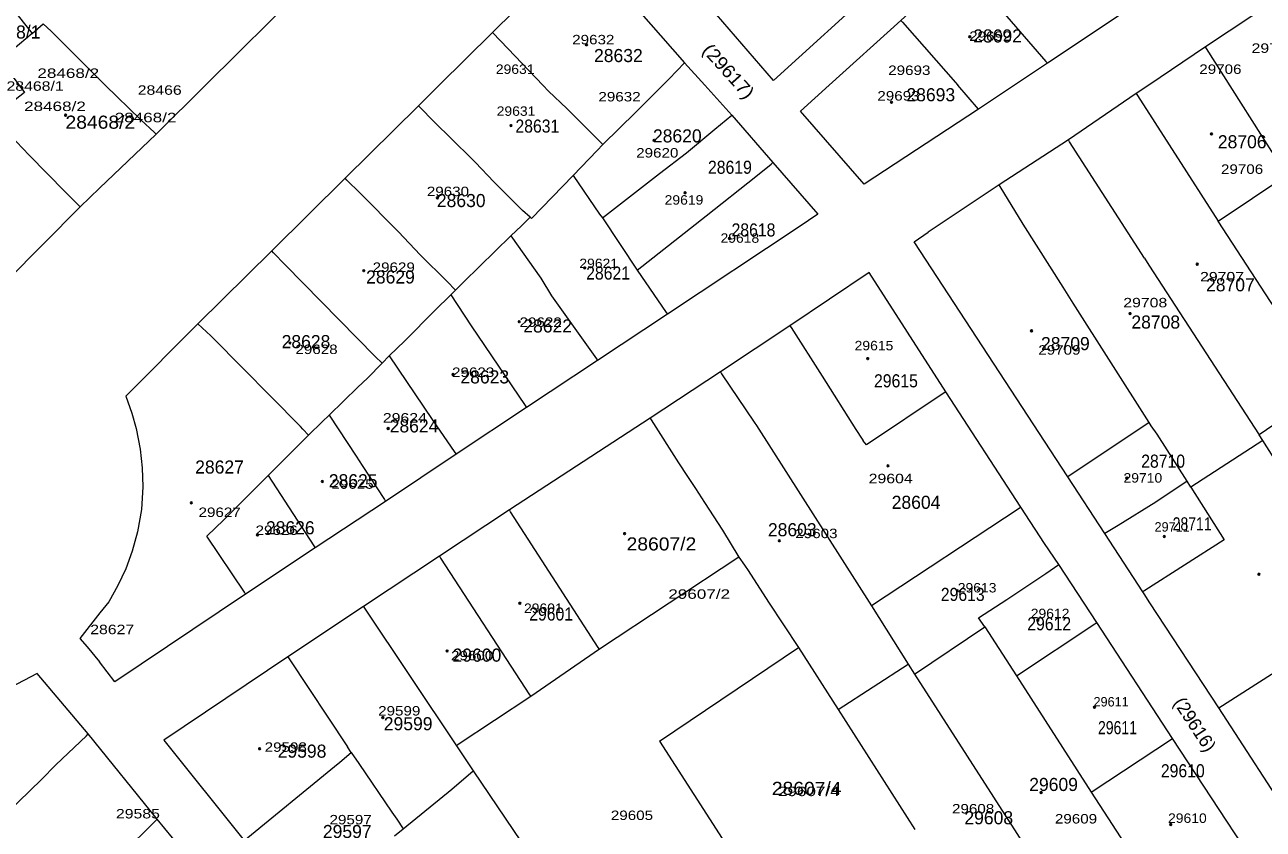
# Model space of a CAD drawing. Extents: x 650553 to 652508, y 239277 to 241647.
# Drawn here: x 651729.3 to 652069.7, y 240545.4 to 240766.6 of the extents above; entities that cross this region are included whole.
import ezdxf

# ---------------------------------------------------------------- set-up
doc = ezdxf.new("R2010")
doc.units = 0
doc.header["$PDMODE"] = 32
doc.header["$PDSIZE"] = 0.5
for name, color, linetype in [('19', 7, 'Continuous'), ('20', 7, 'Continuous'), ('6', 7, 'Continuous')]:
    doc.layers.add(name, color=color, linetype=linetype)
doc.layers.add('3', color=7, linetype='Continuous', lineweight=13)
doc.layers.add('5', color=7, linetype='Continuous', lineweight=13)

msp = doc.modelspace()

# ---------------------------------------------------------------- linework, layer by layer
at = {"layer": '3'}
for p, q in [((651744.578, 240716.581), (651749.871, 240721.656)), ((651746.467, 240595.607), (651749.932, 240591.408)), ((651754.072, 240585.965), (651749.932, 240591.408)), ((651767.56, 240569.86), (651789.69, 240542.31))]:
    msp.add_line(p, q, dxfattribs=at)
for points in [[(651950.46, 240750), (651970.1, 240767.82), (651986.91, 240783.26), (652001.01, 240795.81), (652014.98, 240808.48), (652029.04, 240821.24)], [(652130.48, 240811.26), (652125, 240807.76), (652110.91, 240798.75), (652092.01, 240785.99), (652073.09, 240773.31), (652053.84, 240760.57)], [(651857.87, 240764.46), (651882.29, 240788.58), (651910.691, 240756.161)], [(652058.39, 240788.05), (652042.27, 240777.48), (652026.22, 240766.64), (652010.4, 240756.05)], [(651963.94, 240777.64), (651935.1, 240751.32), (651917.67, 240771.45)], [(651805.82, 240776.71), (651779.01, 240750), (651765.5, 240736.54), (651749.871, 240721.656)], [(651857.87, 240764.46), (651843.25, 240750), (651837.57, 240744.38), (651817.39, 240724.43), (651797.25, 240704.42), (651776.92, 240684.41)], [(652053.84, 240760.57), (652038.24, 240750), (652034.83, 240747.69), (652016.18, 240734.96), (651997.1, 240722.64), (651977.65, 240709.59)], [(651910.691, 240756.161), (651916.23, 240750), (651923.66, 240741.74)], [(652010.4, 240756.05), (652001.33, 240750), (651991.49, 240743.44)], [(651991.49, 240743.44), (651960.07, 240722.77), (651942.55, 240742.83), (651950.46, 240750)], [(651923.66, 240741.74), (651934.97, 240728.71), (651947.34, 240714.57)], [(651666.816, 240692.253), (651670.475, 240694.498), (651675.984, 240697.224), (651681.411, 240699.022), (651686.904, 240700.185), (651694.099, 240701.383), (651699.482, 240701.668), (651705.326, 240701.397), (651710.373, 240700.626), (651715.395, 240699.613), (651720.434, 240697.99), (651724.445, 240696.209), (651744.578, 240716.581)], [(651947.34, 240714.57), (651942.18, 240711.07), (651905.96, 240687.02), (651886.79, 240674.3), (651867.2, 240661.39), (651847.91, 240648.53), (651828.5, 240635.58), (651809.15, 240622.82), (651790.027, 240610.062), (651754.072, 240585.965)], [(652016, 240642.3), (651973.78, 240706.91), (651977.65, 240709.59)], [(652013.5, 240618.17), (652009.59, 240623.96), (652003.11, 240633.96), (651982.48, 240665.71), (651961.39, 240698.5), (651939.62, 240683.88), (651920.51, 240671.17), (651901.2, 240658.49), (651862.54, 240633.2), (651843.29, 240620.48), (651822.42, 240606.7), (651801.69, 240592.79), (651767.56, 240569.86)], [(651776.92, 240684.41), (651757.09, 240664.52), (651758.77, 240659.87), (651759.98, 240655.65), (651761.09, 240649.96), (651761.61, 240644.75), (651761.79, 240639.59), (651761.41, 240633.29), (651760.36, 240627.15), (651758.86, 240621.88), (651757.16, 240616.98), (651754.97, 240612.43), (651752.42, 240607.99), (651750, 240604.91)], [(652057.49, 240578.77), (652038.51, 240607.71), (652036.94, 240610.19), (652036.66, 240610.72), (652026.17, 240626.69), (652016, 240642.3)], [(652044.73, 240570.4), (652023.96, 240602.27), (652013.5, 240618.17)], [(651750, 240604.91), (651744.473, 240597.87), (651746.467, 240595.607)], [(651732.727, 240588.221), (651729.118, 240586.307), (651725.471, 240584.379), (651722.848, 240583.22), (651719.197, 240581.891), (651716.775, 240581.139), (651714.429, 240580.567), (651712.373, 240580.275), (651712.25, 240579.538), (651708.175, 240579.209)], [(651780.52, 240530.19), (651765.75, 240548.18), (651746.79, 240571.618), (651732.727, 240588.221)], [(652100.82, 240560.71), (652078.69, 240546.12), (652057.49, 240578.77)], [(652043.65, 240523), (652066.18, 240537.76), (652044.73, 240570.4)]]:
    msp.add_lwpolyline(points, dxfattribs=at)
at = {"layer": '5'}
for p, q in [((651750, 240751.45), (651751.49, 240750)), ((651991.49, 240743.44), (651985.73, 240750)), ((651730.541, 240730.757), (651720.55, 240741.246)), ((651865.6, 240716.13), (651866.13, 240715.54)), ((651868.23, 240713.72), (651866.13, 240715.54)), ((651948.48, 240670.01), (651957.77, 240655.29)), ((652069.57, 240652.28), (652068.55, 240653.87)), ((651993.19, 240601.05), (652001.94, 240587.56)), ((651952.88, 240578.32), (651974, 240545.35)), ((651789.69, 240542.31), (651814.44, 240562.63)), ((652022.45, 240555.62), (652043.65, 240523))]:
    msp.add_line(p, q, dxfattribs=at)
for points in [[(651986.91, 240783.26), (651987.342, 240782.76), (652009.968, 240756.55), (652010.4, 240756.05)], [(651718.3, 240780.69), (651718.697, 240780.19), (651731.34, 240764.27), (651734.39, 240766.92), (651736.58, 240764.83), (651750, 240751.45)], [(651970.1, 240767.82), (651970.539, 240767.32), (651985.73, 240750)], [(651731.34, 240764.27), (651722.71, 240756.86), (651729.289, 240747.993), (651720.55, 240741.246)], [(651857.87, 240764.46), (651862.22, 240760.01), (651871.73, 240750)], [(652076.22, 240725.27), (652054.157, 240760.07), (652053.84, 240760.57)], [(651904.71, 240750), (651906.48, 240751.76), (651910.691, 240756.161)], [(651765.5, 240736.54), (651765, 240737.001), (651761.25, 240740.46), (651751.49, 240750)], [(651888.25, 240733.71), (651885.65, 240736.28), (651878.32, 240743.59), (651873.27, 240748.38), (651871.73, 240750)], [(651880.04, 240725.22), (651886.64, 240732.01), (651888.25, 240733.71), (651897.3, 240742.64), (651904.71, 240750)], [(652034.83, 240747.69), (652035.151, 240747.19), (652057.31, 240712.66)], [(651841.7, 240740.11), (651838.054, 240743.88), (651837.57, 240744.38)], [(651865.6, 240716.13), (651858.27, 240723.42), (651853.26, 240728.75), (651852.15, 240729.9), (651841.7, 240740.11)], [(651888.08, 240713.51), (651903.8, 240725.71), (651911.17, 240731.38), (651919.02, 240737.96), (651923.66, 240741.74)], [(652037.1, 240702.45), (652016.502, 240734.46), (652016.18, 240734.96)], [(651744.578, 240716.581), (651740.465, 240720.712), (651730.541, 240730.757)], [(651930.25, 240724.94), (651934.47, 240728.311), (651934.97, 240728.71)], [(651821.44, 240720.41), (651817.89, 240723.934), (651817.39, 240724.43)], [(651868.23, 240713.72), (651868.57, 240713.35), (651880.04, 240725.22)], [(651880.04, 240725.22), (651887.27, 240714.51), (651888.08, 240713.51), (651897.63, 240699.15)], [(651897.63, 240699.15), (651916.65, 240714.13), (651930.25, 240724.94)], [(652087.23, 240666.57), (652057.31, 240712.66), (652076.22, 240725.27)], [(651846.43, 240692.37), (651847.72, 240693.68), (651845.46, 240696.06), (651838.05, 240703.4), (651832.05, 240709.67), (651821.44, 240720.41)], [(652003.7, 240711.83), (651997.405, 240722.14), (651997.1, 240722.64)], [(651862.95, 240708.59), (651865.85, 240711.33), (651868.23, 240713.72)], [(652038.38, 240657.23), (652017.48, 240690.05), (652014.73, 240694.44), (652011.03, 240700.23), (652003.7, 240711.83)], [(651847.72, 240693.68), (651850.03, 240695.94), (651862.95, 240708.59), (651871.21, 240696.93), (651874.12, 240692.11)], [(651800.95, 240700.6), (651797.734, 240703.92), (651797.25, 240704.42)], [(651827.55, 240673.6), (651825.68, 240675.45), (651800.95, 240700.6)], [(651897.63, 240699.15), (651905.617, 240687.52), (651905.96, 240687.02)], [(652037.1, 240702.45), (652038.26, 240700.55), (652068.55, 240653.87)], [(651829.53, 240675.62), (651833.78, 240679.76), (651842.08, 240688.08), (651846.43, 240692.37), (651852.05, 240683.86)], [(651874.12, 240692.11), (651886.434, 240674.8), (651886.79, 240674.3)], [(651807.29, 240653.82), (651805.74, 240655.42), (651805.14, 240656.12), (651780.99, 240680.55), (651780.44, 240681.06), (651776.92, 240684.41)], [(651852.05, 240683.86), (651866.863, 240661.89), (651867.2, 240661.39)], [(651939.62, 240683.88), (651939.939, 240683.38), (651948.48, 240670.01)], [(651813.01, 240659.27), (651820.88, 240666.99), (651823.5, 240669.49), (651827.55, 240673.6), (651829.53, 240675.62), (651841.34, 240658.07)], [(651920.51, 240671.17), (651920.848, 240670.67), (651929.83, 240657.38)], [(651982.48, 240665.71), (651981.98, 240665.377), (651960.64, 240651.16), (651960.251, 240651.64), (651959.762, 240652.244)], [(652125, 240607.14), (652087.23, 240666.57), (652068.55, 240653.87)], [(651796.24, 240642.66), (651807.29, 240653.82), (651811.12, 240657.41), (651813.01, 240659.27), (651820.43, 240648.01), (651822.11, 240645.42)], [(651901.2, 240658.49), (651901.519, 240657.99), (651909.04, 240646.21)], [(651841.34, 240658.07), (651847.566, 240649.03), (651847.91, 240648.53)], [(651929.83, 240657.38), (651930.41, 240656.42), (651962.01, 240606.81)], [(651957.77, 240655.29), (651959.503, 240652.64), (651959.762, 240652.244)], [(652048.8, 240641.09), (652040.52, 240654.06), (652038.94, 240656.3), (652038.38, 240657.23), (652016, 240642.3)], [(652057.49, 240578.77), (652079.86, 240593.13), (652099.1, 240605.65), (652069.57, 240652.28), (652049.84, 240639.46)], [(651822.11, 240645.42), (651828.175, 240636.08), (651828.5, 240635.58)], [(651909.04, 240646.21), (651911.45, 240642.39), (651913.67, 240639.07), (651916.16, 240635.23), (651921.09, 240627.61), (651925.63, 240620.27), (651927.18, 240618.02), (651928.13, 240616.53), (651933.75, 240607.84), (651941.96, 240595.43)], [(651784.02, 240630.46), (651789.37, 240635.83), (651796.24, 240642.66)], [(651796.24, 240642.66), (651808.825, 240623.32), (651809.15, 240622.82)], [(652049.84, 240639.46), (652048.8, 240641.09), (652040.21, 240635.39), (652029.8, 240628.89)], [(652049.84, 240639.46), (652058.97, 240624.95), (652037.16, 240611.039), (652036.66, 240610.72)], [(651887.294, 240594.906), (651886.971, 240595.406), (651862.863, 240632.7), (651862.54, 240633.2)], [(652003.11, 240633.96), (652002.61, 240633.63), (651962.01, 240606.81)], [(651790.027, 240610.062), (651789.692, 240610.562), (651779.37, 240625.96), (651784.02, 240630.46)], [(652029.8, 240628.89), (652026.67, 240626.993), (652026.17, 240626.69)], [(651843.29, 240620.48), (651843.615, 240619.98), (651868.076, 240582.401), (651868.401, 240581.901)], [(651925.63, 240620.27), (651887.294, 240594.906), (651868.401, 240581.901)], [(651999.24, 240608.58), (652009.97, 240615.73), (652013.5, 240618.17)], [(651993.19, 240601.05), (651991.48, 240603.59), (651999.24, 240608.58)], [(651822.42, 240606.7), (651822.753, 240606.2), (651847.965, 240568.367), (651852.61, 240561.44)], [(651962.01, 240606.81), (651972.09, 240590.78), (651973.9, 240588.07), (651993.19, 240601.05)], [(652001.94, 240587.56), (652023.46, 240601.936), (652023.96, 240602.27)], [(651903.75, 240569.66), (651941.96, 240595.43), (651952.88, 240578.32), (651972.09, 240590.78)], [(651801.69, 240592.79), (651802.021, 240592.29), (651818.03, 240568.09)], [(651973.9, 240588.07), (652023.66, 240510.43), (652023.98, 240509.93)], [(652001.94, 240587.56), (652022.45, 240555.62), (652044.73, 240570.4)], [(651868.401, 240581.901), (651848.465, 240568.698), (651847.965, 240568.367)], [(651737.908, 240563.103), (651746.29, 240571.139), (651746.79, 240571.618)], [(651814.44, 240562.63), (651815.9, 240563.86), (651819.05, 240566.5), (651818.03, 240568.09)], [(651819.05, 240566.5), (651821.12, 240563.53), (651830.19, 240550.13), (651831.59, 240548.15), (651833.38, 240545.52)], [(651903.75, 240569.66), (651935.56, 240520.19), (651948.78, 240500)], [(651684.3, 240509.906), (651691.776, 240517.523), (651698.788, 240524.311), (651699.785, 240525.447), (651704.534, 240530.177), (651722.068, 240547.369), (651727.626, 240552.993), (651733.93, 240559.128), (651737.908, 240563.103)], [(651831, 240543.63), (651833.38, 240545.52), (651846.72, 240556.46), (651852.61, 240561.44), (651865.79, 240541.92), (651862.49, 240539.35), (651861.77, 240538.68)], [(651765.75, 240548.18), (651765.25, 240547.685), (651756.07, 240538.6), (651749.902, 240532.663)]]:
    msp.add_lwpolyline(points, dxfattribs=at)
at = {"layer": '6'}
for p in [(651883.718, 240761.145), (651989.059, 240763.35), (651967.565, 240745.295), (651740.567, 240741.75), (651862.976, 240738.905), (652055.482, 240736.615), (651902.341, 240734.835), (651910.805, 240720.445), (651842.744, 240719.03), (651923.024, 240707.865), (651822.493, 240699.015), (651883.215, 240699.76), (652051.571, 240700.78), (652033.102, 240687.21), (651865.244, 240684.99), (652006.029, 240682.47), (651802.237, 240679.12), (651961.008, 240674.83), (651847.05, 240670.45), (651829.235, 240655.6), (651966.588, 240645.345), (651811.121, 240641.045), (652032.233, 240641.96), (651775.127, 240635.187), (651793.315, 240626.361), (651894.198, 240626.698), (651936.724, 240624.745), (652042.527, 240625.905), (652068.52, 240615.525), (651985.635, 240611.015), (651865.413, 240607.55), (652007.768, 240602.865), (651845.426, 240594.423), (652023.317, 240578.945), (651827.765, 240576.11), (651793.896, 240567.55), (652008.658, 240555.49), (652044.276, 240546.7)]:
    msp.add_point(p, dxfattribs=at)

# ---------------------------------------------------------------- texts
at = {"layer": '19'}
for s, p in [('28468/1', (651716.245, 240762.834)), ('28692', (651990.006, 240761.756)), ('28632', (651885.794, 240756.368)), ('28693', (651971.647, 240745.591)), ('28620', (651901.992, 240734.275)), ('28706', (652057.232, 240732.659)), ('28630', (651842.596, 240716.495)), ('28629', (651823.158, 240695.481)), ('28707', (652053.993, 240693.325)), ('28622', (651866.355, 240682.009)), ('28708', (652033.473, 240683.087)), ('28628', (651799.939, 240677.699)), ('28709', (652008.636, 240677.16)), ('28623', (651849.076, 240668)), ('28624', (651829.636, 240654.529)), ('28627', (651776.181, 240643.215)), ('28625', (651812.899, 240639.442)), ('28604', (651967.596, 240633.516)), ('28626', (651795.62, 240626.51)), ('28603', (651933.579, 240625.972)), ('29600', (651846.916, 240591.487)), ('29599', (651828.017, 240572.628)), ('29598', (651798.859, 240565.084)), ('29609', (652005.396, 240555.925)), ('29608', (651987.577, 240546.765)), ('29597', (651811.279, 240542.993))]:
    msp.add_text(s, height=3.6, dxfattribs=at).set_placement(p)
at = {"layer": '19', "width": 1.1}
msp.add_text('(29617)', height=3.6, rotation=311.972, dxfattribs=at).set_placement((651915.315, 240759.445))
at = {"layer": '19'}
for s, width, p in [('28468/2', 1.1, (651740.542, 240738.048)), ('28631', 0.9, (651864.196, 240736.97)), ('28619', 0.9, (651917.111, 240725.654)), ('28618', 0.9, (651923.59, 240708.412)), ('28621', 0.9, (651883.634, 240696.558)), ('29615', 0.9, (651962.739, 240666.923)), ('28710', 0.9, (652036.173, 240644.831)), ('28711', 0.8, (652044.813, 240627.588)), ('28607/2', 1.1, (651894.745, 240622.066)), ('29613', 0.9, (651981.097, 240608.191)), ('29601', 0.9, (651867.976, 240602.802)), ('29612', 0.9, (652004.856, 240600.109)), ('29611', 0.8, (652024.295, 240571.551)), ('29610', 0.9, (652041.573, 240559.697)), ('28607/4', 1.1, (651934.658, 240554.847))]:
    msp.add_text(s, height=3.6, dxfattribs=dict(at, width=width)).set_placement(p)
msp.add_text('(29616)', height=3.6, rotation=303.093, dxfattribs=at).set_placement((652044.894, 240580.221))
at = {"layer": '20'}
for s, width, p in [('29632', 1.2, (651879.791, 240761.248)), ('29692', 1.2, (651988.89, 240762.205)), ('29705', 1.25, (652066.496, 240758.902)), ('28468/2', 1.35, (651732.817, 240752.015)), ('29631', 1.1, (651858.803, 240753.111)), ('29693', 1.2, (651966.641, 240752.825)), ('29706', 1.2, (652052.129, 240753.118)), ('28468/1', 1.25, (651724.332, 240748.48)), ('28466', 1.25, (651760.391, 240747.379)), ('29632', 1.2, (651886.995, 240745.549)), ('29693', 1.2, (651963.659, 240745.793)), ('28468/2', 1.35, (651729.16, 240742.904)), ('29631', 1.1, (651859.04, 240741.588)), ('28468/2', 1.35, (651754.063, 240739.827)), ('29620', 1.2, (651897.375, 240730.115)), ('29706', 1.2, (652058.093, 240725.629)), ('29630', 1.2, (651839.845, 240719.506)), ('29619', 1.1, (651905.198, 240717.16)), ('29618', 1.1, (651920.555, 240706.68)), ('29629', 1.2, (651824.954, 240698.666)), ('29621', 1.1, (651881.759, 240699.717)), ('29707', 1.25, (652052.342, 240696.056)), ('29708', 1.25, (652031.242, 240688.927)), ('29622', 1.2, (651865.331, 240683.545)), ('29628', 1.2, (651803.727, 240676.084)), ('29615', 1.1, (651957.411, 240677.106)), ('29709', 1.2, (652007.889, 240675.908)), ('29623', 1.2, (651846.776, 240669.784)), ('29624', 1.25, (651827.761, 240657.241)), ('29625', 1.2, (651813.621, 240639.033)), ('29604', 1.25, (651961.28, 240640.555)), ('29710', 1.1, (652031.301, 240640.732)), ('29627', 1.2, (651777.105, 240631.276)), ('29626', 1.2, (651792.774, 240626.325)), ('29603', 1.2, (651941.111, 240625.458)), ('29607/2', 1.35, (651906.208, 240608.782)), ('29613', 1.1, (651985.759, 240610.524)), ('29601', 1.1, (651866.548, 240604.892)), ('29612', 1.1, (652005.809, 240603.453)), ('28627', 1.25, (651747.335, 240599.052)), ('29600', 1.2, (651846.494, 240591.857)), ('29599', 1.2, (651826.463, 240576.675)), ('29598', 1.2, (651795.278, 240566.698)), ('29607/4', 1.35, (651936.334, 240554.519)), ('29585', 1.25, (651754.4, 240548.382)), ('29597', 1.2, (651813.101, 240546.744)), ('29605', 1.2, (651890.418, 240547.944)), ('29608', 1.2, (651984.175, 240549.755)), ('29609', 1.2, (652012.448, 240546.988)), ('29610', 1.1, (652043.539, 240547.161))]:
    msp.add_text(s, height=2.6, dxfattribs=dict(at, width=width)).set_placement(p)
for s, p in [('29711', (652039.837, 240627.248)), ('29611', (652023.06, 240579.169))]:
    msp.add_text(s, height=2.6, dxfattribs=at).set_placement(p)

doc.saveas('drawing.dxf')
